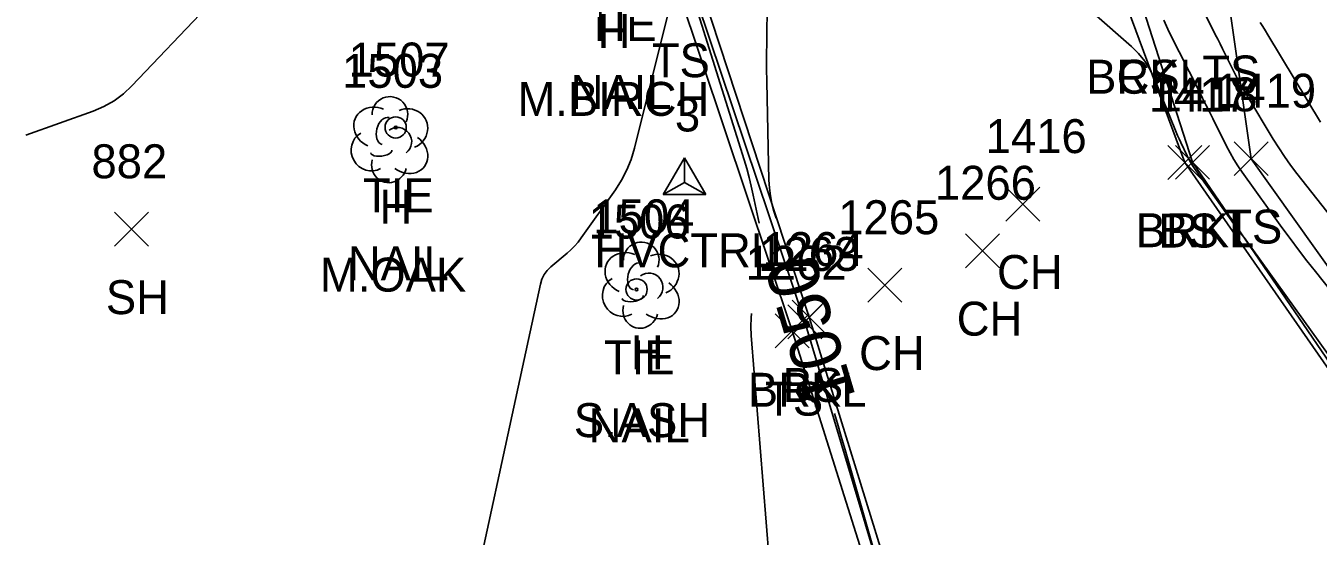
# Model space of a CAD drawing. Extents: x 1592612 to 1596497, y 111838 to 113741.
# Drawn here: x 1592847.3 to 1592923.4, y 113332 to 113362.1 of the extents above; entities that cross this region are included whole.
import ezdxf

# ---------------------------------------------------------------- set-up
doc = ezdxf.new("R2010")
doc.units = 0
for name, color, linetype in [('C_A', 7, 'Continuous'), ('C_C', 7, 'Continuous'), ('C_I', 7, 'Continuous'), ('CBP', 7, 'Continuous'), ('CPSM', 7, 'Continuous'), ('L_A', 7, 'Continuous'), ('L_C', 7, 'Continuous'), ('L_I', 7, 'Continuous'), ('L_TIC', 7, 'Continuous'), ('LAWE', 7, 'Continuous'), ('LELB', 7, 'Continuous'), ('LSOGCMA', 7, 'Continuous'), ('LSOGCMA_T', 7, 'Continuous'), ('LSOGCMI', 7, 'Continuous'), ('LTD', 7, 'Continuous')]:
    doc.layers.add(name, color=color, linetype=linetype)

msp = doc.modelspace()

# ---------------------------------------------------------------- linework, layer by layer
at = {"layer": 'CBP'}
for centre, radius in [((1592869.091, 113356.104), 0.625), ((1592869.091, 113356.104), 0.0833), ((1592883.275, 113346.565), 0.625), ((1592883.275, 113346.565), 0.0833)]:
    msp.add_circle(centre, radius, dxfattribs=at)
at = {"layer": 'CPSM'}
for p, q in [((1592884.85, 113352.148), (1592886.1, 113354.313)), ((1592887.35, 113352.148), (1592886.1, 113354.313)), ((1592886.1, 113352.869), (1592886.1, 113354.313)), ((1592884.85, 113352.148), (1592886.1, 113352.869)), ((1592886.1, 113352.869), (1592886.1, 113352.869)), ((1592886.1, 113352.869), (1592887.35, 113352.148)), ((1592884.85, 113352.148), (1592887.35, 113352.148))]:
    msp.add_line(p, q, dxfattribs=at)
at = {"layer": 'L_TIC'}
for points in [[(1592914.557, 113353.032), (1592916.557, 113355.032)], [(1592916.557, 113353.032), (1592914.557, 113355.032)], [(1592915.015, 113353.051), (1592917.015, 113355.051)], [(1592917.015, 113353.051), (1592915.015, 113355.051)], [(1592918.468, 113353.266), (1592920.468, 113355.266)], [(1592920.468, 113353.266), (1592918.468, 113355.266)], [(1592905.012, 113350.594), (1592907.012, 113352.594)], [(1592907.012, 113350.594), (1592905.012, 113352.594)], [(1592852.538, 113349.111), (1592854.538, 113351.111)], [(1592854.538, 113349.111), (1592852.538, 113351.111)], [(1592902.637, 113347.845), (1592904.637, 113349.845)], [(1592904.637, 113347.845), (1592902.637, 113349.845)], [(1592896.889, 113345.817), (1592898.889, 113347.817)], [(1592898.889, 113345.817), (1592896.889, 113347.817)], [(1592892.179, 113343.656), (1592894.179, 113345.656)], [(1592894.179, 113343.656), (1592892.179, 113345.656)], [(1592892.431, 113343.94), (1592894.431, 113345.94)], [(1592894.431, 113343.94), (1592892.431, 113345.94)], [(1592891.434, 113343.134), (1592893.434, 113345.134)], [(1592893.434, 113343.134), (1592891.434, 113345.134)]]:
    msp.add_lwpolyline(points, dxfattribs=at)
at = {"layer": 'LAWE'}
for points in [[(1592867.923, 113458.263), (1592869.843, 113440.453), (1592871.967, 113422.356), (1592872.93, 113405.001), (1592883.346, 113373.9), (1592893.179, 113344.656), (1592901.657, 113316.308), (1592912.684, 113311.087), (1592910.248, 113308.35), (1592916.07, 113291.076)], [(1593001.92, 113269.875), (1592980.168, 113281.757), (1592972.077, 113292.77), (1592952.739, 113309.006), (1592930.405, 113333.014), (1592916.015, 113354.051), (1592913.1, 113363.091), (1592910.596, 113379.281), (1592906.825, 113388.644), (1592902.208, 113400.349), (1592897.68, 113413.914), (1592895.157, 113422.89), (1592891.073, 113425.248), (1592889.456, 113425.542), (1592888.74, 113438.019), (1592887.745, 113444.76), (1592887.496, 113453.354)]]:
    msp.add_lwpolyline(points, dxfattribs=at)
at = {"layer": 'LELB'}
for points in [[(1592866.59, 113458.717), (1592868.12, 113440.226), (1592870.678, 113422.668), (1592871.235, 113404.668), (1592883.079, 113373.124), (1592885.764, 113364.063), (1592892.434, 113344.134), (1592901.184, 113316.355)], [(1592873.192, 113458.509), (1592876.893, 113440.279), (1592874.766, 113422.722), (1592874.598, 113405.543), (1592883.851, 113374.09), (1592893.431, 113344.94), (1592902.258, 113316.43), (1592913.374, 113311.383), (1592911.324, 113309.219), (1592917.546, 113291.093), (1592922.314, 113282.948), (1592911.412, 113283.497), (1592902.691, 113283.749), (1592891.129, 113289.026)], [(1593000.607, 113268.02), (1592979.237, 113281.269), (1592969.817, 113290.666), (1592952.505, 113308.706), (1592930.32, 113332.83), (1592915.558, 113354.032), (1592906.593, 113378.229), (1592901.651, 113400.349), (1592897.345, 113413.71), (1592894.471, 113422.658), (1592891.543, 113424.972)], [(1593002.844, 113271.334), (1592982.233, 113284.253), (1592973.366, 113294.033), (1592954.604, 113311.113), (1592933.333, 113334.792), (1592919.468, 113354.266), (1592918.171, 113363.34), (1592916.481, 113374.12), (1592914.915, 113386.717)]]:
    msp.add_lwpolyline(points, dxfattribs=at)
at = {"layer": 'LSOGCMA'}
for points in [[(1592891.045, 113365.88), (1592890.951, 113361.938), (1592890.937, 113361.153), (1592890.931, 113360.369), (1592890.934, 113359.584), (1592890.946, 113358.799), (1592891.068, 113353.009), (1592891.094, 113352.543), (1592891.152, 113352.082), (1592891.242, 113351.626), (1592891.365, 113351.175), (1592891.493, 113350.76)], [(1592928.423, 113336.599), (1592919.05, 113349.617), (1592919.035, 113349.636), (1592919.02, 113349.655), (1592919.004, 113349.673), (1592918.988, 113349.69), (1592918.92, 113349.758), (1592918.904, 113349.775), (1592918.888, 113349.793), (1592918.873, 113349.812), (1592918.859, 113349.831), (1592916.135, 113353.689), (1592916.013, 113353.869), (1592915.899, 113354.055), (1592915.792, 113354.245), (1592915.694, 113354.44), (1592915.315, 113355.228), (1592915.222, 113355.425), (1592915.132, 113355.624), (1592915.046, 113355.825), (1592914.962, 113356.027), (1592913.768, 113358.968), (1592913.514, 113359.505), (1592913.203, 113360.003), (1592912.836, 113360.46), (1592912.412, 113360.878), (1592907.821, 113364.914)], [(1592894.934, 113339.263), (1592895.105, 113338.668), (1592895.326, 113337.898), (1592895.548, 113337.127), (1592898.314, 113327.501)]]:
    msp.add_lwpolyline(points, dxfattribs=at)
at = {"layer": 'LSOGCMI'}
for points in [[(1592890.498, 113350.465), (1592890.147, 113352.124), (1592890.03, 113352.646), (1592889.901, 113353.165), (1592889.759, 113353.68), (1592889.605, 113354.192), (1592884.626, 113370.074)], [(1592847.314, 113355.654), (1592851.274, 113357.072), (1592851.913, 113357.343), (1592852.507, 113357.681), (1592853.056, 113358.087), (1592853.562, 113358.56), (1592857.972, 113363.187)], [(1592885.13, 113362.836), (1592883.145, 113354.876), (1592882.951, 113354.227), (1592882.699, 113353.604), (1592882.391, 113353.007), (1592882.025, 113352.437), (1592880.017, 113349.605), (1592879.829, 113349.357), (1592879.627, 113349.123), (1592879.41, 113348.902), (1592879.179, 113348.695), (1592878.224, 113347.893), (1592878.007, 113347.679), (1592877.833, 113347.44), (1592877.702, 113347.174), (1592877.614, 113346.882), (1592872.292, 113322.344)], [(1592914.32, 113362.429), (1592914.637, 113361.706), (1592916.392, 113358.236), (1592916.596, 113357.833), (1592916.799, 113357.43), (1592917.001, 113357.026), (1592917.203, 113356.623), (1592918.009, 113355.008), (1592918.219, 113354.609), (1592918.444, 113354.219), (1592918.684, 113353.839), (1592918.94, 113353.468), (1592921.277, 113350.222), (1592921.758, 113349.561), (1592922.247, 113348.907), (1592922.744, 113348.259), (1592923.248, 113347.616), (1592932.269, 113336.256)], [(1592931.733, 113341.271), (1592922.159, 113353.397), (1592921.785, 113353.886), (1592921.427, 113354.386), (1592921.085, 113354.897), (1592920.759, 113355.42), (1592919.203, 113358.002), (1592919.03, 113358.295), (1592918.863, 113358.592), (1592918.702, 113358.892), (1592918.547, 113359.195), (1592917.913, 113360.463), (1592917.773, 113360.743), (1592917.633, 113361.023), (1592917.492, 113361.302), (1592917.351, 113361.582), (1592916.786, 113362.699)], [(1592919.994, 113362.281), (1592920.151, 113362.04), (1592920.304, 113361.796), (1592920.454, 113361.55), (1592923.553, 113356.41)], [(1592891.794, 113321.863), (1592890.029, 113343.855), (1592890.006, 113344.374), (1592890.02, 113344.891), (1592890.046, 113345.148)]]:
    msp.add_lwpolyline(points, dxfattribs=at)
at = {"layer": 'LTD'}
for p, q in [((1592868.705, 113355.438), (1592868.705, 113355.438)), ((1592868.705, 113355.438), (1592868.705, 113355.438)), ((1592883.502, 113346.869), (1592883.502, 113346.869)), ((1592883.502, 113346.869), (1592883.502, 113346.869))]:
    msp.add_line(p, q, dxfattribs=at)
for centre in [(1592868.752, 113356.872), (1592883.549, 113348.303)]:
    msp.add_arc(centre, 1.047, 335.52715, 180.95627, dxfattribs=at)
for centre, major_axis, ratio, start_param, end_param in [((1592867.914, 113356.105), (1.21, -0.512), 0.895232, 1.570796, 4.712389), ((1592869.747, 113356.022), (-1.141, -0.483), 0.949671, 1.570796, 4.712389), ((1592868.497, 113355.896), (-0.208, -0.792), 0.645439, 3.141593, 6.283185), ((1592869.205, 113355.272), (-0.5, 0.667), 0.989748, 3.141593, 6.283185), ((1592867.622, 113354.73), (0.584, -1.042), 0.959034, 3.141593, 6.283185), ((1592869.706, 113354.605), (-1.09, 0.792), 0.841452, 1.570796, 4.712389), ((1592868.247, 113354.688), (-0.625, -0.083), 0.423636, 0, 3.141593), ((1592868.706, 113353.938), (0.265, 1.061), 0.942809, 1.570796, 4.712389), ((1592882.711, 113347.535), (1.21, -0.512), 0.895232, 1.570796, 4.712389), ((1592884.544, 113347.452), (-1.141, -0.483), 0.949671, 1.570796, 4.712389), ((1592883.294, 113347.327), (-0.208, -0.792), 0.645439, 3.141593, 6.283185), ((1592882.419, 113346.16), (0.584, -1.042), 0.959034, 3.141593, 6.283185), ((1592884.002, 113346.702), (-0.5, 0.667), 0.989748, 3.141593, 6.283185), ((1592884.503, 113346.036), (-1.09, 0.792), 0.841452, 1.570796, 4.712389), ((1592883.503, 113345.369), (0.265, 1.061), 0.942809, 1.570796, 4.712389), ((1592883.044, 113346.119), (-0.625, -0.083), 0.423636, 0, 3.141593)]:
    msp.add_ellipse(centre, major_axis=major_axis, ratio=ratio, start_param=start_param, end_param=end_param, dxfattribs=at)

# ---------------------------------------------------------------- texts
at = {"layer": 'C_A'}
for s, p in [('TIE', (1592880.287, 113361.199)), ('TIE', (1592867.17, 113351.104)), ('HVCTRL', (1592880.793, 113347.869)), ('TIE', (1592881.353, 113341.565))]:
    msp.add_text(s, height=2, dxfattribs=at).set_placement(p)
at = {"layer": 'C_C'}
for p in [(1592879.389, 113357.199), (1592866.272, 113347.104), (1592880.456, 113337.565)]:
    msp.add_text('NAIL', height=2, dxfattribs=at).set_placement(p)
at = {"layer": 'C_I'}
for s, p in [('1507', (1592866.319, 113359.104)), ('3', (1592885.533, 113355.869)), ('1506', (1592880.448, 113349.565))]:
    msp.add_text(s, height=2, dxfattribs=at).set_placement(p)
at = {"layer": 'L_A'}
for s, p in [('H', (1592880.987, 113360.785)), ('TS', (1592884.173, 113359.063)), ('BRKL', (1592909.745, 113358.091)), ('CS', (1592911.541, 113358.091)), ('TS', (1592916.581, 113358.34)), ('H', (1592868.139, 113350.438)), ('BRKL', (1592912.661, 113349.051)), ('BS', (1592913.998, 113349.032)), ('TS', (1592917.878, 113349.266)), ('CH', (1592904.501, 113346.594)), ('SH', (1592852.026, 113345.111)), ('CH', (1592902.125, 113343.845)), ('H', (1592882.935, 113341.869)), ('CH', (1592896.377, 113341.817)), ('BS', (1592891.872, 113339.94)), ('BRKL', (1592889.825, 113339.656)), ('TS', (1592890.843, 113339.134))]:
    msp.add_text(s, height=2, dxfattribs=at).set_placement(p)
at = {"layer": 'L_C'}
for s, p in [('M.BIRCH', (1592876.263, 113356.785)), ('M.OAK', (1592864.627, 113346.438)), ('S.ASH', (1592879.581, 113337.869))]:
    msp.add_text(s, height=2, dxfattribs=at).set_placement(p)
at = {"layer": 'L_I'}
for s, p in [('1503', (1592865.934, 113358.438)), ('1419', (1592917.335, 113357.266)), ('1417', (1592913.432, 113357.032)), ('1418', (1592913.889, 113357.051)), ('1416', (1592903.831, 113354.594)), ('882', (1592851.176, 113353.111)), ('1266', (1592900.841, 113351.845)), ('1504', (1592880.731, 113349.869)), ('1265', (1592895.149, 113349.817)), ('1263', (1592890.439, 113347.656)), ('1264', (1592890.691, 113347.94)), ('1262', (1592889.694, 113347.134))]:
    msp.add_text(s, height=2, dxfattribs=at).set_placement(p)
at = {"layer": 'LSOGCMA_T'}
for s, rotation, p in [('1060', 299.71155, (1592921.995, 113367.233)), ('1050', 106.51723, (1592896.199, 113340.23))]:
    msp.add_text(s, height=3, rotation=rotation, dxfattribs=at).set_placement(p)

doc.saveas('drawing.dxf')
